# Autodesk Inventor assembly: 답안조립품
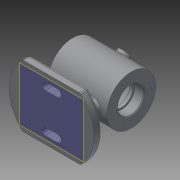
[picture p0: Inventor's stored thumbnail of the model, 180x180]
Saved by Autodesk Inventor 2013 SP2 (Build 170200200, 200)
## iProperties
Created: 2022-02
Part Number: 답안조립품
Document SubType Name: Assembly
Designer: a
Author: a
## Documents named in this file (2)
- C:\Users\a\Desktop\720206V1020\답안조립품.iam
- C:\Users\a\Desktop\720206V1020\본체.ipt
